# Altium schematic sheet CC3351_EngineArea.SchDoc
size A2; Date: Not shown in title block; ApprovedBy: Not shown in title block; CheckedBy: Not shown in title block; Author: Not shown in title block; CompanyName: Not shown in title block; Engineer: Not shown in title block; Organization: Not shown in title block; Address1: Not shown in title block; Address2: Not shown in title block; Address3: Not shown in title block; Address4: Not shown in title block; DocumentNumber: 1; Revision: Use project parameter SCH_Rev; SheetNumber: 1; SheetTotal: 1; PageSetup: Record=PageOptions¦CenterHorizontal=True¦CenterVertical=True¦PrintScale=0.69¦XCorrection=1.00¦YCorrection=1.00¦PrintKind=0¦BorderSize=5000000¦LeftOffset=0¦BottomOffset=0¦Orientation=2¦PaperLength=1000¦PaperWidth=1000¦Scale=100¦PaperSource=15¦PrintQuality=600¦MediaType=1¦DitherType=10¦PaperKind=Letter¦PrintScaleMode=1
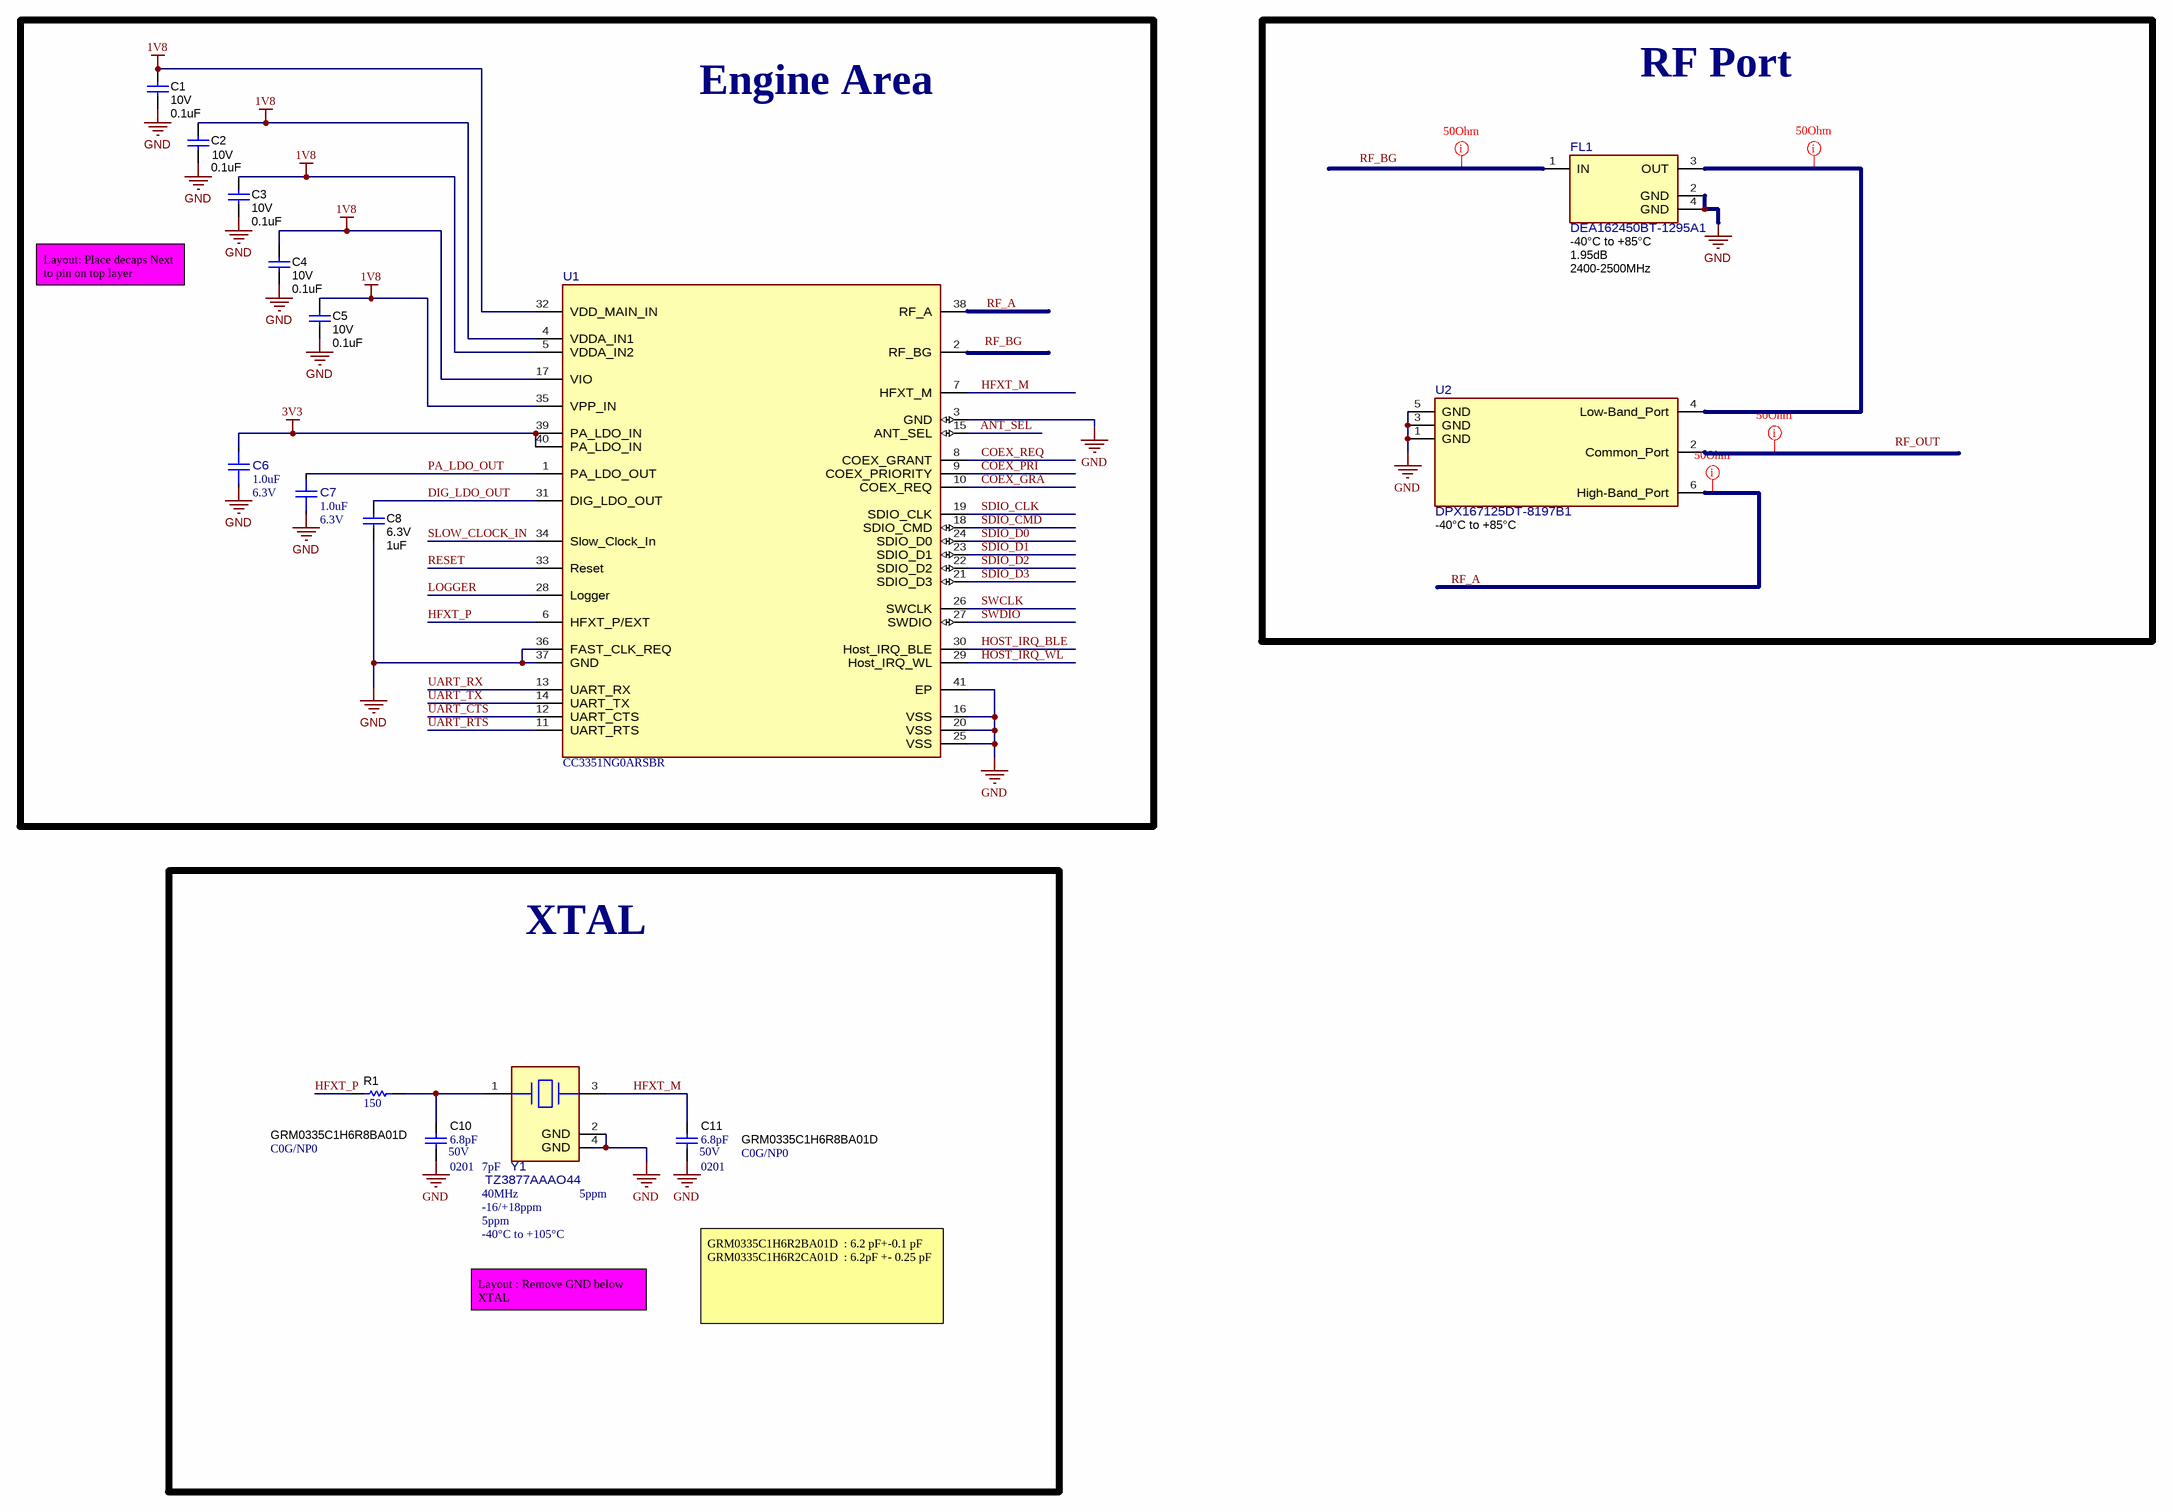
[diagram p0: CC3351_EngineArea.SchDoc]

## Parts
C1  VDC_V: 10V  ValueDisplayed: 0.1uF  [0201]  (hidden comment: GRM033C71A104KE14D)
C2  VDC_V: 10V  ValueDisplayed: 0.1uF  [0201]  (hidden comment: GRM033C71A104KE14D)
C3  VDC_V: 10V  ValueDisplayed: 0.1uF  [0201]  (hidden comment: GRM033C71A104KE14D)
C4  VDC_V: 10V  ValueDisplayed: 0.1uF  [0201]  (hidden comment: GRM033C71A104KE14D)
C5  VDC_V: 10V  ValueDisplayed: 0.1uF  [0201]  (hidden comment: GRM033C71A104KE14D)
C6  ValueDisplayed: 1.0uF  VDC_V: 6.3V  [FP-GRM033D70J105ME01D_0201-MFG]  (hidden comment: GRM033D70J105ME01D)
C7  ValueDisplayed: 1.0uF  VDC_V: 6.3V  [FP-GRM033D70J105ME01D_0201-MFG]  (hidden comment: GRM033D70J105ME01D)
C8  VDC_V: 6.3V  ValueDisplayed: 1uF  [0402]  (hidden comment: GRM155R70J105MA12D)
C10  GRM0335C1H6R8BA01D  TempCo: C0G/NP0  VDC_V: 50V  ValueDisplayed: 6.8pF  [0201]
C11  GRM0335C1H6R8BA01D  TempCo: C0G/NP0  VDC_V: 50V  ValueDisplayed: 6.8pF  [0201]
FL1  DEA162450BT-1295A1  Operating Temperature Range: -40°C to +85°C  Bandwidth: 2400-2500MHz  Insertion Loss: 1.95dB  [FP-DEA162450BT-1295A1_SMT_FILTER_1MM60_0MM80-MFG]
R1  ValueDisplayed: 150  [0201]  (hidden comment: RC0201FS-7D150RL)
U1  CC3351NG0ARSBR  [RSB0040B-MFG]
U2  DPX167125DT-8197B1  Operating Temperature Range: -40°C to +85°C  [FP-DPX167125DT-8197B1_SMD6-MFG]
Y1  TZ3877AAAO44  Tolerance_%: 5ppm  Operating Temperature Range: -40°C to +105°C  Load Capacitance: 7pF  Frequency Stability: -16/+18ppm  Frequency_Fixed: 40MHz  [FP-TZ3877AAAO44_SMT4_2MM05_1MM65-MFG]

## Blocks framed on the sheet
Engine Area: C1-C8 U1
RF Port: FL1 U2
XTAL: C10 C11 R1 Y1

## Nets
1V8: C1.1 C2.1 C3.1 C4.1 C5.1 U1.4(VDDA_IN1) U1.5(VDDA_IN2) U1.17(VIO) U1.32(VDD_MAIN_IN) U1.35(VPP_IN)
3V3: C6.2 U1.39(PA_LDO_IN) U1.40(PA_LDO_IN)
GND: C1.2 C2.2 C3.2 C4.2 C5.2 C6.1 C7.1 C8.2 C10.2 C11.2 FL1.2(GND) FL1.4(GND) U1.3(GND) U1.16(VSS) U1.20(VSS) U1.25(VSS) U1.36(FAST_CLK_REQ) U1.37(GND) U1.41(EP) U2.1(GND) U2.3(GND) U2.5(GND) Y1.2(GND) Y1.4(GND)
ANT_SEL: U1.15(ANT_SEL)
COEX_GRA: U1.10(COEX_REQ)
COEX_PRI: U1.9(COEX_PRIORITY)
COEX_REQ: U1.8(COEX_GRANT)
DIG_LDO_OUT: C8.1 U1.31(DIG_LDO_OUT)
HFXT_M: C11.1 U1.7(HFXT_M) Y1.3(2_IN/OUT)
HFXT_P: R1.1 U1.6(HFXT_P/EXT)
HOST_IRQ_BLE: U1.30(Host_IRQ_BLE)
HOST_IRQ_WL: U1.29(Host_IRQ_WL)
LOGGER: U1.28(Logger)
PA_LDO_OUT: C7.2 U1.1(PA_LDO_OUT)
RESET: U1.33(Reset)
RF_A: U2.6(High-Band_Port)
SDIO_CLK: U1.19(SDIO_CLK)
SDIO_CMD: U1.18(SDIO_CMD)
SDIO_D0: U1.24(SDIO_D0)
SDIO_D1: U1.23(SDIO_D1)
SDIO_D2: U1.22(SDIO_D2)
SDIO_D3: U1.21(SDIO_D3)
SLOW_CLOCK_IN: U1.34(Slow_Clock_In)
SWCLK: U1.26(SWCLK)
SWDIO: U1.27(SWDIO)
UART_CTS: U1.12(UART_CTS)
UART_RTS: U1.11(UART_RTS)
UART_RX: U1.13(UART_RX)
UART_TX: U1.14(UART_TX)
NetC10_1: C10.1 R1.2 Y1.1(1_IN/OUT)
NetFL1_3: FL1.3(OUT) U2.4(Low-Band_Port)

Not connected (* = marked no-connect by the designer): FL1 1(IN); U1 2(RF_BG) 38(RF_A); U2 2(Common_Port)

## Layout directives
rule Undefined; net class RF: NetFL1_1, NetFL1_3, NetU2_2, RF_A

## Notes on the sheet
- Layout: Place decaps Next to pin on top layer
- Layout : Remove GND below XTAL
- GRM0335C1H6R2BA01D  : 6.2 pF+-0.1 pF
  GRM0335C1H6R2CA01D  : 6.2pF +- 0.25 pF
- Labels drawn without touching a wire or pin: RF_BG, RF_OUT

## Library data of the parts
C1-C5 = CMP-0064969-1: CAP, CERM, 0.1 uF, 10 V,+/- 10%, X7S, 0201; Manufacturer: MuRata; TaMin_C: -55°C; Polarized: N; SizeAreaWB_mm2: 2.08; Value1: Unknown; U/M: EA; Value: 0.1uF; TaMax_C: 125°C; SizeZ_mm: 0.26; SizeX_mm: 0.6; SizeY_mm: 0.3; SizeArea_mm2: 0.18; Cap_F: 100nF; AEC Category: Q200
C6 C7 = CMP-0095016-1: Chip Multilayer Ceramic Capacitors for General Purpose, 0201, 1.0uF, X7T, +22%/-33%, 20%, 6.3V; Manufacturer: Murata; Cap_F: 1µF; AEC Qualified: No; Value: 1µF; SizeZ_mm: 0.39mm
C8 = CMP-0006624-2: CAP, CERM, 1 uF, 6.3 V, +/- 20%, X7R, 0402; Manufacturer: MuRata; TaMin_C: -55°C; Polarized: N; SizeAreaWB_mm2: 3; Value1: Unknown; U/M: EA; Value: 1uF; TaMax_C: 125°C; SizeZ_mm: 0.6; SizeX_mm: 1; SizeY_mm: 0.5; Cap_F: 1µF; AEC Category: Q200
C10 C11 = CMP-0009669-4: CAP, CERM, 6.8 pF, 50 V, +/- 2%, C0G/NP0, 0201; Manufacturer: MuRata; TaMin_C: -55°C; Polarized: N; SizeAreaWB_mm2: 2.08; Value1: Unknown; U/M: EA; Value: 6.8pF; TaMax_C: 125°C; SizeZ_mm: 0.26; SizeX_mm: 0.6; SizeY_mm: 0.3; SizeArea_mm2: 0.18; AEC Category: Q200
FL1 = CMP-0091509-1: 2.45GHz Center Frequency Band Pass RF Filter (Radio Frequency) 100MHz Bandwidth 1.8dB 0603 (1608 Metric), 3 PC Pad; Manufacturer: TDK; AEC Qualified: No; SizeZ_mm: 0.7mm
R1 = CMP-0028078-1: RES, 150, 1%, 0.05 W, 0201; Manufacturer: Yageo America; Power_W: 50mW; TempCo: 200 ppm/C; Value_Code: 150R; U/M: EA; Value: 150; EIA_Code: E96; SizeX_mm: 0.6; SizeY_mm: 0.3; SizeZ_mm: 0.26; Value2: 0.05W; SizeArea_mm2: 0.18; AEC Qualified: N; VDC_V: 25V; AEC Category: Q200
U1 = CMP-0094602-1: Manufacturer: Texas Instruments; Part Number: CC3301NG0ARSBR; Standoff Height: 0mm; SizeZ_mm: 0.8mm
U2 = CMP-0091972-1: Multilayer Diplexer For 2.4-2.5GHz W-LAN & Bluetooth / 5-7GHz W-LAN; Manufacturer: TDK; Insertion Loss: 1dB; SizeZ_mm: 0.7mm; AEC Qualified: No
Y1 = CMP-0094297-1: Crystal Unit SMD 2.0x1.6 40.0MHz; Manufacturer: TAI-SAW TECHNOLOGY; SizeZ_mm: 0.5mm; Esr: 30; AEC Qualified: No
